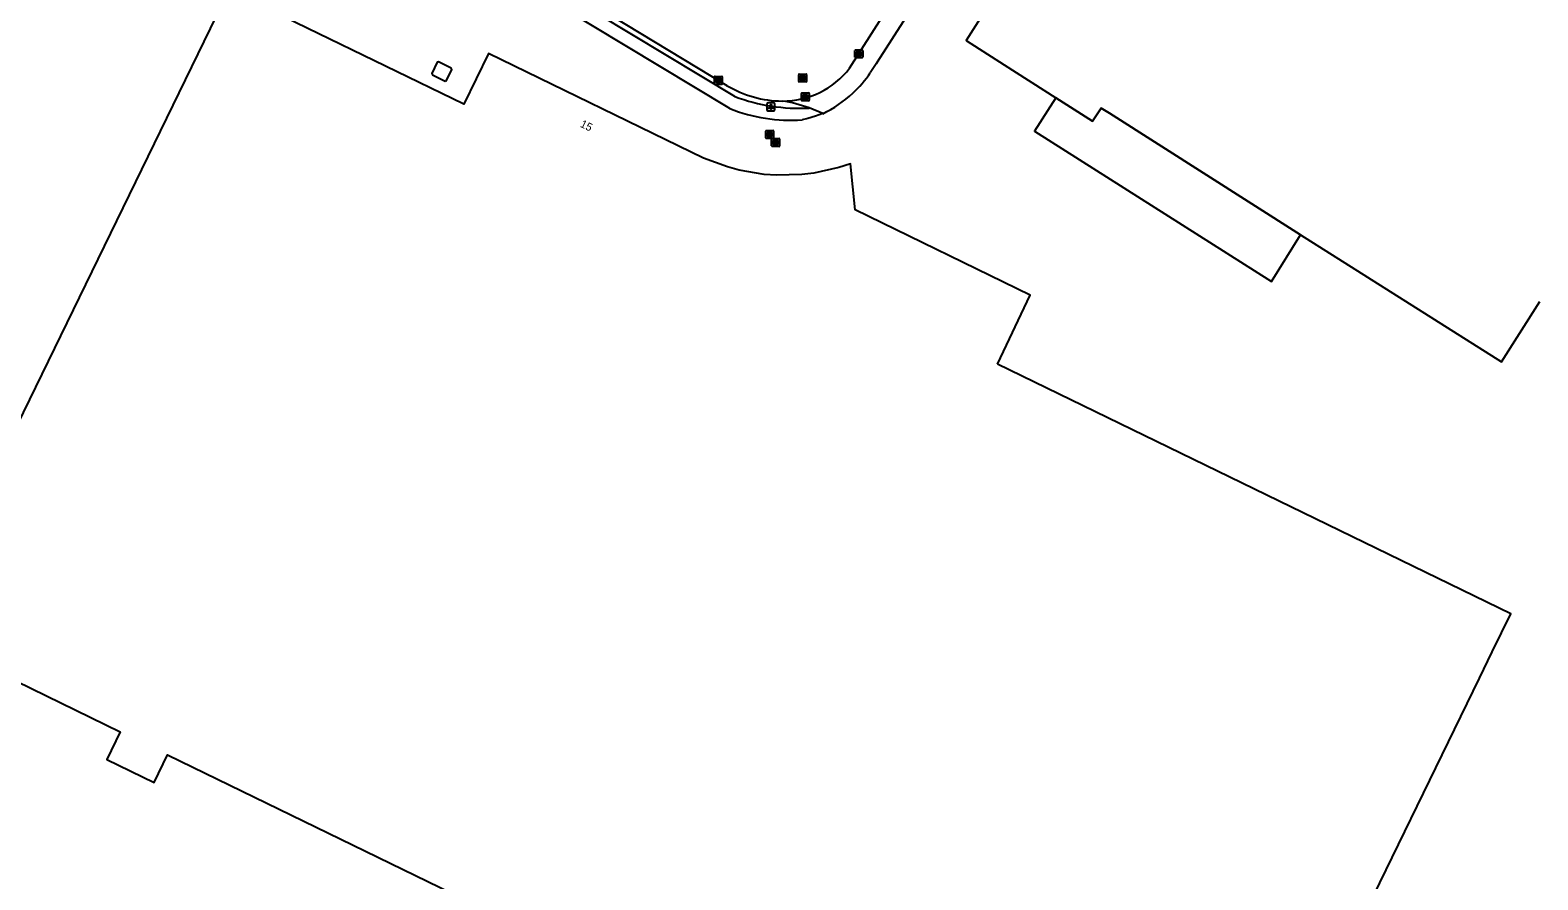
# Model space of a CAD drawing. Extents: x 156141 to 158132, y 385651 to 388399.
# Drawn here: x 156511.2 to 156702, y 386510.1 to 386617.7 of the extents above; entities that cross this region are included whole.
import ezdxf

# ---------------------------------------------------------------- set-up
doc = ezdxf.new("R2010")
doc.units = 0
for name, color, linetype in [('IMGEO_Kolk', 7, 'Continuous'), ('IMGEO_Lage_trafo', 7, 'Continuous'), ('IMGEO_Lichtpunt', 7, 'Continuous'), ('IMGEO_Pand', 7, 'Continuous'), ('IMGEO_Pand_nummerreeks', 7, 'Continuous'), ('IMGEO_Pand_overbouw', 7, 'Continuous'), ('IMGEO_Rijbaan_lokaal_gesloten', 7, 'Continuous'), ('IMGEO_Rioolput', 7, 'Continuous'), ('IMGEO_Voetpad_open', 7, 'Continuous')]:
    doc.layers.add(name, color=color, linetype=linetype)

msp = doc.modelspace()

# ---------------------------------------------------------------- linework, layer by layer
at = {"layer": 'IMGEO_Kolk'}
for p, q in [((156615.56, 386614.26), (156615.56, 386615.11)), ((156615.64, 386615.18), (156616.49, 386615.18)), ((156616.05, 386614.96), (156616.08, 386614.96)), ((156616.56, 386615.11), (156616.56, 386614.26)), ((156616.49, 386614.18), (156615.64, 386614.18)), ((156616.07, 386614.4), (156616.05, 386614.4)), ((156597.79, 386610.9), (156597.79, 386611.75)), ((156597.86, 386611.82), (156598.72, 386611.82)), ((156598.72, 386610.82), (156597.86, 386610.82)), ((156598.28, 386611.6), (156598.3, 386611.6)), ((156598.3, 386611.04), (156598.28, 386611.04)), ((156598.79, 386611.75), (156598.79, 386610.9))]:
    msp.add_line(p, q, dxfattribs=at)
for points in [[(156615.56, 386614.26), (156615.56, 386615.11)], [(156615.64, 386615.18), (156616.49, 386615.18)], [(156615.88, 386614.88), (156616.01, 386614.88), (156616.01, 386614.73), (156616.14, 386614.88), (156616.3, 386614.88), (156616.16, 386614.73), (156616.31, 386614.48), (156616.16, 386614.48), (156616.07, 386614.65), (156616.01, 386614.58), (156616.01, 386614.48), (156615.88, 386614.48), (156615.88, 386614.88)], [(156616.56, 386615.11), (156616.56, 386614.26)], [(156616.49, 386614.18), (156615.64, 386614.18)], [(156597.79, 386610.9), (156597.79, 386611.75)], [(156597.86, 386611.82), (156598.72, 386611.82)], [(156598.72, 386610.82), (156597.86, 386610.82)], [(156598.11, 386611.52), (156598.23, 386611.52), (156598.23, 386611.37), (156598.36, 386611.52), (156598.53, 386611.52), (156598.38, 386611.37), (156598.53, 386611.12), (156598.38, 386611.12), (156598.3, 386611.29), (156598.23, 386611.22), (156598.23, 386611.12), (156598.11, 386611.12), (156598.11, 386611.52)], [(156598.79, 386611.75), (156598.79, 386610.9)]]:
    msp.add_lwpolyline(points, dxfattribs=at)
for centre, start, end in [((156615.64, 386615.11), 91.552, 178.448), ((156615.64, 386615.11), 91.552, 178.448), ((156616.49, 386615.11), 1.552, 88.448), ((156616.49, 386615.11), 1.552, 88.448), ((156615.64, 386614.26), 181.552, 268.448), ((156615.64, 386614.26), 181.552, 268.448), ((156616.49, 386614.26), 271.552, 358.448), ((156616.49, 386614.26), 271.552, 358.448), ((156597.87, 386611.75), 91.552, 178.448), ((156597.87, 386611.75), 91.552, 178.448), ((156597.87, 386610.9), 181.552, 268.448), ((156597.87, 386610.9), 181.552, 268.448), ((156598.71, 386611.75), 1.552, 88.448), ((156598.71, 386611.75), 1.552, 88.448), ((156598.71, 386610.9), 271.552, 358.448), ((156598.71, 386610.9), 271.552, 358.448)]:
    msp.add_arc(centre, 0.0765, start, end, dxfattribs=at)
for centre, major_axis, ratio, start_param, end_param in [((156616.05, 386614.68), (-0.387, 0.002), 0.722429, 4.712389, 7.853982), ((156616.07, 386614.68), (-0.39, 0.002), 0.717154, 1.570796, 4.712389), ((156598.28, 386611.32), (-0.387, 0.002), 0.722429, 4.712389, 7.853982), ((156598.3, 386611.32), (-0.39, 0.002), 0.717154, 1.570796, 4.712389)]:
    msp.add_ellipse(centre, major_axis=major_axis, ratio=ratio, start_param=start_param, end_param=end_param, dxfattribs=at)
at = {"layer": 'IMGEO_Lage_trafo'}
msp.add_lwpolyline([(156563.7, 386611.24), (156563.87, 386611.3), (156564.57, 386612.72), (156564.49, 386612.88), (156562.88, 386613.67), (156562.72, 386613.62), (156562.03, 386612.19), (156562.09, 386612.02), (156563.7, 386611.24)], dxfattribs=at)
at = {"layer": 'IMGEO_Lichtpunt'}
for p, q in [((156604.44, 386608.36), (156604.44, 386607.56)), ((156604.44, 386608.36), (156604.44, 386607.56)), ((156605.34, 386608.46), (156604.54, 386608.46)), ((156605.34, 386608.46), (156604.54, 386608.46)), ((156604.54, 386607.46), (156605.34, 386607.46)), ((156604.54, 386607.46), (156605.34, 386607.46)), ((156605.44, 386607.56), (156605.44, 386608.36)), ((156605.44, 386607.56), (156605.44, 386608.36))]:
    msp.add_line(p, q, dxfattribs=at)
for points in [[(156604.82, 386608.03), (156604.85, 386608), (156604.67, 386607.74), (156604.63, 386607.76), (156604.82, 386608.03)], [(156604.92, 386607.98), (156604.97, 386607.98), (156604.97, 386607.66), (156604.92, 386607.66), (156604.92, 386607.98)], [(156605.03, 386608), (156605.07, 386608.03), (156605.25, 386607.76), (156605.21, 386607.74), (156605.03, 386608)]]:
    msp.add_lwpolyline(points, dxfattribs=at)
msp.add_circle((156604.94, 386608.16), 0.0994, dxfattribs=at)
for centre, start, end in [((156604.54, 386608.36), 90, 180), ((156604.54, 386608.36), 90, 180), ((156604.54, 386607.56), 180, 270), ((156604.54, 386607.56), 180, 270), ((156605.34, 386608.36), 0, 90), ((156605.34, 386608.36), 0, 90), ((156605.34, 386607.56), 270, 0), ((156605.34, 386607.56), 270, 360)]:
    msp.add_arc(centre, 0.0946, start, end, dxfattribs=at)
at = {"layer": 'IMGEO_Pand'}
for points in [[(156707.54, 386628.94), (156699.05, 386634.33), (156694.32, 386637.32), (156680.44, 386646.14), (156677.95, 386647.72), (156673.75, 386650.39), (156674.83, 386652.09), (156670.6, 386654.77), (156663.36, 386659.38), (156663.25, 386659.2), (156658.86, 386661.99), (156654.04, 386654.39), (156653.85, 386654.51), (156629.64, 386616.37), (156634.44, 386613.27), (156641, 386609.11), (156645.65, 386606.15), (156646.75, 386607.82), (156647.78, 386607.17), (156671.97, 386591.75), (156697.38, 386575.67), (156702.23, 386583.31)], [(156633.6, 386575.41), (156637.75, 386584.14), (156615.6, 386594.93), (156614.99, 386600.74), (156613.54, 386600.28), (156610.38, 386599.59), (156608.85, 386599.4), (156605.63, 386599.31), (156604.09, 386599.42), (156600.91, 386599.95), (156599.43, 386600.36), (156596.41, 386601.47), (156569.21, 386614.73), (156566.09, 386608.32), (156536.34, 386622.8), (156500, 386548.21)], [(156677.27, 386500), (156694.62, 386535.65), (156696.23, 386538.95), (156698.58, 386543.77), (156633.6, 386575.41)], [(156500, 386539.86), (156522.6, 386528.85), (156520.89, 386525.35), (156526.88, 386522.43), (156528.59, 386525.93), (156581.8, 386500)]]:
    msp.add_lwpolyline(points, dxfattribs=at)
at = {"layer": 'IMGEO_Pand_overbouw'}
msp.add_lwpolyline([(156641, 386609.11), (156639.96, 386607.48), (156638.3, 386604.88), (156668.28, 386585.87), (156671.97, 386591.75), (156647.78, 386607.17), (156646.75, 386607.82), (156645.65, 386606.15)], close=True, dxfattribs=at)
at = {"layer": 'IMGEO_Rijbaan_lokaal_gesloten'}
for points in [[(156516.21, 386660.93), (156516.42, 386660.8), (156528.8, 386653.32), (156544.88, 386643.61), (156561.56, 386633.56), (156577.37, 386624), (156599.34, 386610.69)], [(156614.9, 386612.85), (156623.35, 386626.22)]]:
    msp.add_lwpolyline(points, dxfattribs=at)
for centre, radius, start, end in [((156606.38, 386619.52), 10.82, 269.9931, 321.9755), ((156606.51, 386622.61), 13.91, 238.9658, 269.4382)]:
    msp.add_arc(centre, radius, start, end, dxfattribs=at)
at = {"layer": 'IMGEO_Rioolput'}
for p, q in [((156608.46, 386611.19), (156608.46, 386612.04)), ((156608.53, 386612.12), (156609.38, 386612.12)), ((156609.38, 386611.12), (156608.53, 386611.12)), ((156608.97, 386611.34), (156608.94, 386611.34)), ((156608.95, 386611.9), (156608.97, 386611.9)), ((156609.46, 386612.04), (156609.46, 386611.19)), ((156608.79, 386608.81), (156608.79, 386609.66)), ((156608.86, 386609.73), (156609.72, 386609.73)), ((156609.72, 386608.73), (156608.86, 386608.73)), ((156609.28, 386609.51), (156609.3, 386609.51)), ((156609.3, 386608.95), (156609.28, 386608.95)), ((156609.79, 386609.66), (156609.79, 386608.81)), ((156604.28, 386604.05), (156604.28, 386604.9)), ((156604.35, 386604.97), (156605.21, 386604.97)), ((156605.28, 386604.9), (156605.28, 386604.05)), ((156605.21, 386603.97), (156604.35, 386603.97)), ((156604.79, 386604.19), (156604.76, 386604.19)), ((156604.77, 386604.75), (156604.79, 386604.75)), ((156605.03, 386603.03), (156605.03, 386603.88)), ((156605.1, 386603.96), (156605.95, 386603.96)), ((156605.51, 386603.74), (156605.54, 386603.74)), ((156605.54, 386603.18), (156605.51, 386603.18)), ((156606.03, 386603.88), (156606.03, 386603.03)), ((156605.95, 386602.96), (156605.1, 386602.96))]:
    msp.add_line(p, q, dxfattribs=at)
for points in [[(156608.46, 386611.19), (156608.46, 386612.04)], [(156608.53, 386612.12), (156609.38, 386612.12)], [(156609.38, 386611.12), (156608.53, 386611.12)], [(156609.05, 386611.81), (156608.79, 386611.82), (156608.79, 386611.42)], [(156608.79, 386611.42), (156608.92, 386611.42), (156608.92, 386611.58), (156608.93, 386611.58)], [(156608.97, 386611.74), (156608.92, 386611.74), (156608.92, 386611.65)], [(156608.92, 386611.65), (156608.97, 386611.65)], [(156608.98, 386611.55), (156609.05, 386611.42), (156609.19, 386611.42), (156609.12, 386611.54)], [(156609.46, 386612.04), (156609.46, 386611.19)], [(156608.79, 386608.81), (156608.79, 386609.66)], [(156608.86, 386609.73), (156609.72, 386609.73)], [(156609.72, 386608.73), (156608.86, 386608.73)], [(156609.38, 386609.43), (156609.13, 386609.43), (156609.13, 386609.03)], [(156609.13, 386609.03), (156609.25, 386609.03), (156609.25, 386609.19), (156609.26, 386609.19)], [(156609.31, 386609.35), (156609.25, 386609.35), (156609.25, 386609.27)], [(156609.25, 386609.27), (156609.3, 386609.27)], [(156609.31, 386609.16), (156609.38, 386609.03), (156609.52, 386609.03), (156609.45, 386609.16)], [(156609.79, 386609.66), (156609.79, 386608.81)], [(156604.28, 386604.05), (156604.28, 386604.9)], [(156604.35, 386604.97), (156605.21, 386604.97)], [(156605.28, 386604.9), (156605.28, 386604.05)], [(156605.21, 386603.97), (156604.35, 386603.97)], [(156604.87, 386604.67), (156604.61, 386604.67), (156604.61, 386604.27)], [(156604.61, 386604.27), (156604.74, 386604.27), (156604.74, 386604.44), (156604.75, 386604.44)], [(156604.79, 386604.59), (156604.74, 386604.59), (156604.74, 386604.51)], [(156604.74, 386604.51), (156604.79, 386604.51)], [(156604.8, 386604.41), (156604.87, 386604.27), (156605.01, 386604.27), (156604.94, 386604.4)], [(156605.03, 386603.03), (156605.03, 386603.88)], [(156605.1, 386603.96), (156605.95, 386603.96)], [(156605.62, 386603.65), (156605.36, 386603.66), (156605.36, 386603.26)], [(156605.36, 386603.26), (156605.49, 386603.26), (156605.49, 386603.42), (156605.5, 386603.42)], [(156605.54, 386603.58), (156605.49, 386603.58), (156605.49, 386603.49)], [(156605.49, 386603.49), (156605.54, 386603.49)], [(156605.54, 386603.39), (156605.62, 386603.26), (156605.76, 386603.26), (156605.69, 386603.38)], [(156606.03, 386603.88), (156606.03, 386603.03)], [(156605.95, 386602.96), (156605.1, 386602.96)]]:
    msp.add_lwpolyline(points, dxfattribs=at)
for centre, radius, start, end in [((156608.53, 386612.04), 0.0765, 91.552, 178.448), ((156608.53, 386612.04), 0.0765, 91.552, 178.448), ((156608.53, 386611.19), 0.0765, 181.552, 268.448), ((156608.53, 386611.19), 0.0765, 181.552, 268.448), ((156608.93, 386611.53), 0.0533, 26.0293, 88.6989), ((156608.98, 386611.64), 0.0964, 77.0061, 93.1865), ((156608.95, 386611.84), 0.19, 274.7715, 282.9687), ((156608.99, 386611.7), 0.0378, 276.6634, 79.6772), ((156609.05, 386611.71), 0.109, 350.3612, 89.416), ((156609.04, 386611.7), 0.112, 277.5842, 350.9817), ((156609.03, 386611.49), 0.108, 29.5134, 73.7905), ((156609.38, 386612.04), 0.0765, 1.552, 88.448), ((156609.38, 386612.04), 0.0765, 1.552, 88.448), ((156609.38, 386611.19), 0.0765, 271.552, 358.448), ((156609.38, 386611.19), 0.0765, 271.552, 358.448), ((156608.87, 386609.66), 0.0765, 91.552, 178.448), ((156608.87, 386609.66), 0.0765, 91.552, 178.448), ((156608.87, 386608.81), 0.0765, 181.552, 268.448), ((156608.87, 386608.81), 0.0765, 181.552, 268.448), ((156609.26, 386609.14), 0.0533, 26.0293, 88.6989), ((156609.29, 386609.46), 0.19, 274.7715, 282.9687), ((156609.31, 386609.25), 0.0964, 77.0061, 93.1865), ((156609.33, 386609.31), 0.0378, 276.6634, 79.6772), ((156609.38, 386609.32), 0.109, 350.3612, 89.416), ((156609.38, 386609.32), 0.112, 277.5842, 350.9817), ((156609.36, 386609.1), 0.108, 29.5134, 73.7905), ((156609.71, 386609.66), 0.0765, 1.552, 88.448), ((156609.71, 386609.66), 0.0765, 1.552, 88.448), ((156609.71, 386608.81), 0.0765, 271.552, 358.448), ((156609.71, 386608.81), 0.0765, 271.552, 358.448), ((156604.35, 386604.9), 0.0765, 91.552, 178.448), ((156604.35, 386604.9), 0.0765, 91.552, 178.448), ((156605.2, 386604.9), 0.0765, 1.552, 88.448), ((156605.2, 386604.9), 0.0765, 1.552, 88.448), ((156604.35, 386604.05), 0.0765, 181.552, 268.448), ((156604.35, 386604.05), 0.0765, 181.552, 268.448), ((156604.75, 386604.38), 0.0533, 26.0293, 88.6989), ((156604.8, 386604.5), 0.0964, 77.0061, 93.1865), ((156604.78, 386604.7), 0.19, 274.7715, 282.9687), ((156604.81, 386604.55), 0.0378, 276.6634, 79.6772), ((156604.87, 386604.56), 0.109, 350.3612, 89.416), ((156604.86, 386604.56), 0.112, 277.5842, 350.9817), ((156604.85, 386604.35), 0.108, 29.5134, 73.7905), ((156605.1, 386603.88), 0.0765, 91.552, 178.448), ((156605.1, 386603.88), 0.0765, 91.552, 178.448), ((156605.1, 386603.03), 0.0765, 181.552, 268.448), ((156605.1, 386603.03), 0.0765, 181.552, 268.448), ((156605.2, 386604.05), 0.0765, 271.552, 358.448), ((156605.2, 386604.05), 0.0765, 271.552, 358.448), ((156605.5, 386603.37), 0.0533, 26.0293, 88.6989), ((156605.55, 386603.48), 0.0964, 77.0061, 93.1865), ((156605.52, 386603.68), 0.19, 274.7715, 282.9687), ((156605.56, 386603.54), 0.0378, 276.6634, 79.6772), ((156605.61, 386603.54), 0.109, 350.3612, 89.416), ((156605.61, 386603.54), 0.112, 277.5842, 350.9817), ((156605.6, 386603.33), 0.108, 29.5134, 73.7905), ((156605.95, 386603.88), 0.0765, 1.552, 88.448), ((156605.95, 386603.88), 0.0765, 1.552, 88.448), ((156605.95, 386603.03), 0.0765, 271.552, 358.448), ((156605.95, 386603.03), 0.0765, 271.552, 358.448)]:
    msp.add_arc(centre, radius, start, end, dxfattribs=at)
for centre, major_axis, ratio, start_param, end_param in [((156608.94, 386611.62), (-0.387, 0.002), 0.722429, 4.712389, 7.853982), ((156608.97, 386611.62), (-0.39, 0.002), 0.717154, 1.570796, 4.712389), ((156609.28, 386609.23), (-0.387, 0.002), 0.722429, 4.712389, 7.853982), ((156609.3, 386609.23), (-0.39, 0.002), 0.717154, 1.570796, 4.712389), ((156604.77, 386604.47), (-0.387, 0.002), 0.722429, 4.712389, 7.853982), ((156604.79, 386604.47), (-0.39, 0.002), 0.717154, 1.570796, 4.712389), ((156605.51, 386603.46), (-0.387, 0.002), 0.722429, 4.712389, 7.853982), ((156605.54, 386603.46), (-0.39, 0.002), 0.717154, 1.570796, 4.712389)]:
    msp.add_ellipse(centre, major_axis=major_axis, ratio=ratio, start_param=start_param, end_param=end_param, dxfattribs=at)
at = {"layer": 'IMGEO_Voetpad_open'}
for points in [[(156600.38, 386609.28), (156574.3, 386625.03), (156542.74, 386644.08), (156515.39, 386660.56)], [(156599.76, 386607.76), (156573.46, 386623.64), (156541.9, 386642.7), (156513.2, 386660.01)], [(156623.81, 386622.16), (156618.39, 386613.61), (156618.25, 386613.4), (156618, 386613.02), (156617.52, 386612.28)], [(156611.52, 386607.11), (156610.56, 386606.79), (156609.6, 386606.49), (156608.89, 386606.34)], [(156611.52, 386607.11), (156609.79, 386607.83)]]:
    msp.add_lwpolyline(points, dxfattribs=at)
for centre, radius, start, end in [((156605.71, 386620.22), 14.23, 312.3169, 326.0795), ((156608.54, 386631.02), 23.23, 249.4196, 273.0762), ((156604.09, 386592.61), 16.25, 69.4855, 81.9207), ((156604.73, 386621.05), 15.51, 295.9682, 312.9587), ((156607.37, 386626.66), 20.38, 248.0476, 274.2611)]:
    msp.add_arc(centre, radius, start, end, dxfattribs=at)

# ---------------------------------------------------------------- texts
at = {"layer": 'IMGEO_Pand_nummerreeks'}
msp.add_text('15', height=1, rotation=334.0106, dxfattribs=at).set_placement((156580.71, 386605.48))

doc.saveas('drawing.dxf')
